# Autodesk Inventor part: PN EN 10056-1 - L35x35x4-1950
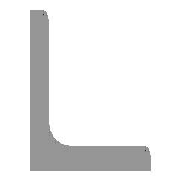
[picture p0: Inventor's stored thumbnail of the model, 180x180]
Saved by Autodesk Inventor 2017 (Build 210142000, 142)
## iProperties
Created: 2016-02
Part Number: PN EN 10056-1 - L35x35x4-1950
Material: Stal, miękka
Description: Kątownik równoramienny
Document SubType Name: Modeling
Standard: PN
Designer: X
Standards Organization: PN
Language: pl-PL
Size Designation: L35x35x4
Categories: <MemberInstance><Categories><Category DisplayName="Kształtowniki konstrukcyjne" InternalName="089c4875-fa83-4c05-b084-43b9cc11f5ed" Mnemonic="GRDR"><CategoryPar
Stock Number: L35x35x4
Density: 7.85 g/cm^3
Appearance: Częściowo polerowana
_CCFamilyMember: 60
_CCFamilyDisplayName: PN EN 10056-1 (Kątownik równoramienny) - Kątownik równoramienny
_FrameMemberDoc: Frame Member File
_Version: 15.0.0
_GetPNFromCC: 1
G_L: 1950,000 mm
G_W: 35,000 mm
G_H: 35,000 mm
IsCustomPart: 1
Author: X
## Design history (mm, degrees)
node "Płaszczyzna początkowa"
node "Płaszczyzna końcowa"
sketch "Szkic2"
  geometry: L1 (-6.019, -1.019)-(-6.019, 22.481); L2 (-10.019, 24.981)-(-8.519, 24.981); L3 (-10.019, -10.019)-(-10.019, 24.981); L4 (-10.019, -10.019)-(24.981, -10.019); L5 (24.981, -8.519)-(24.981, -10.019); L6 (-1.019, -6.019)-(22.481, -6.019); L7 (0, 28.185)-(0, -14.54) reference; L8 (-14.54, 0)-(28.185, 0) reference; A1 r 5 centre (-1.019, -1.019) between (-6.019, -1.019) and (-1.019, -6.019); A2 r 2.5 centre (-8.519, 22.481) between (-6.019, 22.481) and (-8.519, 24.981); A3 r 2.5 centre (22.481, -8.519) between (24.981, -8.519) and (22.481, -6.019); 3 further points
  constraints: 12 end point, 6 point on circle, 6 point on line, 6 tangent, 3 centre point, 3 horizontal, 3 vertical, 1 equal radius
  dimensions: "d4" = 35 distance of L3.start L4.end (= b); "d6" = 35 distance of L3.start L2.start (= b); "d8" = 4 distance of point (24.981, -6.019) L4.end (= ParT); "d10" = 4 distance of L2.start point (-6.019, 24.981) (= ParT); "d17" = 5 radius of A1 (= R); "d18" = 2.5 radius of A2 (= R1); "d19" = 10.01931 distance between parallel lines of L8 L4 (= ex); "d20" = 10.01931 distance between parallel lines of L3 L7 (= d19)
extrude "Bryła" new body sketch "Szkic2" stored distance "d11" = 1950 (= G_L); taper "d12" = 0 deg
node "Driven Length"
  sketch "Sketch3"
    geometry: L1 (0, 0)-(10, 0) reference
    constraints: 2 end point, 1 horizontal
  workplane "Work Plane10"
  sketch "Sketch4"
    geometry: L1 (-2, 0)-(12, 0) reference; L2 (-2, 1950)-(12, 1950) reference
    dimensions: "d24" = 1950 distance between parallel lines of L1 L2 (derived)
body "Solid1"
other parameters: "b" = 35 [user parameter; used in 3 equation terms], "ParT" = 4 [user parameter; used in 3 equation terms], "R" = 5 [user parameter; used in 1 equation term], "R1" = 2.5 [user parameter; used in 1 equation term], "G_L" = 1950 (= d24) [user parameter; used in 1 equation term], "d7" = 4 (derived), "d9" = 4 (derived), "ex" = 10.01931 (computed from b, ParT) [user parameter; used in 1 equation term], "G_OFFSET_START" = 0 [user parameter; used in 1 equation term], "G_OFFSET_END" = 0 [user parameter; used in 1 equation term], "d21" = 0 (computed from G_OFFSET_START), "d23" = 90 deg
